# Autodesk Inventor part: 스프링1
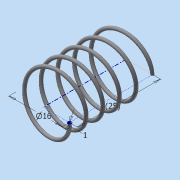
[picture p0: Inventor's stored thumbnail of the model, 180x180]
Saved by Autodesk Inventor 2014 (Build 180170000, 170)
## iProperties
Created: 2015-06
Part Number: 스프링1
Material: 강철, 연강
Document SubType Name: Modeling
Designer: Administrator
Density: 7.86 g/cm^3
Appearance: 강철
Mass: 1.53479 g
Surface Area: 7.89194 cm^2
Volume: 0.195266 cm^3
Author: Administrator
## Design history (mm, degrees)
sketch "스케치1"
  geometry: L1 (0, 0)-(8, 0); L2 (8, 0)-(8, 21.5); L3 (8, 21.5)-(0, 21.5); L4 (0, 21.5)-(0, 0); C1 r 0.5 at (8, 0)
  constraints: 8 end point, 2 parallel, 1 centre point, 1 coincident, 1 horizontal, 1 perpendicular
  dimensions: "d0" = 1 diameter of C1; "d1" = 16 diameter of L2 L4; "d2" = 21.5 distance of L1.end L2.end (derived)
feature "코일1" sketch "스케치1" pitch "d3" = 10; turns "d5" = 5; dims "d4" = 21.5 (= d2), "d6" = 0, angle "d7" = 90 deg, angle "d8" = 90 deg, "d9" = 0, "d10" = 0
sketch "스케치2"
  geometry: L1 (-8.5, 0)-(-7.5, 0) reference; 1 further point
  constraints: 1 horizontal alignment
extrude "돌출1" cut sketch "스케치2" distance "d11" = 10; taper "d12" = 0 deg
node "작업 평면1"
sketch "스케치3"
  geometry: L1 (-7.5, 0)-(-8.5, 0) reference; 1 further point
  constraints: 1 horizontal alignment
extrude "돌출2" cut sketch "스케치3" distance "d14" = 10; taper "d15" = 0 deg
node "솔리드1"
node "절단 모서리 투영1"
node "절단 모서리 투영2"
other parameters: "d13" = 21.5 (= d2)
